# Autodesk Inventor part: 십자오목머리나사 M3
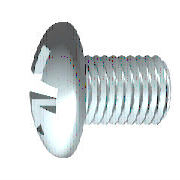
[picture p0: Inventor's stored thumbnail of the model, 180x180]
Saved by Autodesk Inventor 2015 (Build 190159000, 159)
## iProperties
Created: 2012-02
Part Number: 십자오목머리나사 M3
Material: 강철, 연강
Description: 십자 오목 머리 나사
Document SubType Name: Modeling
Standard: KS B 1023
Designer: mduedu
Standards Organization: KS
Language: ko-KR
Size Designation: A  M 3 x 6 - H
Categories: <MemberInstance><Categories><Category DisplayName="조임쇠" InternalName="e4da775c-781d-43d5-af7c-5136215cf5a6" Mnemonic="FSTN"><Category DisplayName="볼트" InternalN
Density: 7.86 g/cm^3
Appearance: 강철
Mass: 0.662353 g
Surface Area: 1.40196 cm^2
Volume: 0.0842689 cm^3
IsCustomPart: 0
Author: mduedu
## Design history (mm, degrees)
body "Solid1"
workplane "Work Plane3"
sketch "스케치2"
  geometry: L1 (-3.72, 0)-(3.72, 0) reference; L2 (0, -3.72)-(0, 3.72) reference; L3 (0, 1.5)-(0, 0); L4 (0, 0)-(1.5, 0); L5 (0, 0)-(1.879, 1.879); L6 (0.253, 1.479)-(0.261, 0.456); L7 (1.479, 0.253)-(0.456, 0.261); L8 (0.253, -1.479)-(0.261, -0.456); L9 (1.479, -0.253)-(0.456, -0.261); L10 (-0.253, 1.479)-(-0.261, 0.456); L11 (-1.479, 0.253)-(-0.456, 0.261); L12 (-1.479, -0.253)-(-0.456, -0.261); L13 (-0.253, -1.479)-(-0.261, -0.456); A1 r 0.45 centre (0, 0) between (0.45, 0) and (0, 0.45); A2 r 1.5 centre (0, 0) between (1.5, 0) and (1.479, 0.253); A3 r 1.5 centre (0, 0) between (0.253, 1.479) and (0, 1.5); A4 r 1.5 centre (0, 0) between (1.479, 0.253) and (0.253, 1.479); A5 r 1.5 centre (0, 0) between (0, -1.5) and (0.253, -1.479); A6 r 1.5 centre (0, 0) between (0.253, -1.479) and (1.479, -0.253); A7 r 1.5 centre (0, 0) between (1.479, -0.253) and (1.5, 0); A8 r 1.5 centre (0, 0) between (-1.479, 0.253) and (-1.5, 0); A9 r 1.5 centre (0, 0) between (-0.253, 1.479) and (-1.479, 0.253); A10 r 1.5 centre (0, 0) between (0, 1.5) and (-0.253, 1.479); A11 r 1.5 centre (0, 0) between (-1.5, 0) and (-1.479, -0.253); A12 r 1.5 centre (0, 0) between (-1.479, -0.253) and (-0.253, -1.479); A13 r 1.5 centre (0, 0) between (-0.253, -1.479) and (0, -1.5); A14 r 0.525 centre (0, 0) between (0.525, 0) and (0, 0.525); A15 r 0.197 centre (0.457, 0.457) between (0.261, 0.456) and (0.456, 0.261); A16 r 0.197 centre (0.457, -0.457) between (0.456, -0.261) and (0.261, -0.456); A17 r 0.197 centre (-0.457, 0.457) between (-0.456, 0.261) and (-0.261, 0.456); A18 r 0.197 centre (-0.457, -0.457) between (-0.261, -0.456) and (-0.456, -0.261); 1 further point
  constraints: 38 point on circle, 22 end point, 19 symmetric about line, 18 centre point, 4 coincident, 3 collinear, 3 point on line, 3 tangent, 1 perpendicular, 21 other
  dimensions: "d4" = 45 deg angle of L5 L4; "d5" = 0.9 diameter of A1 (= 0.3 x SDM); "d6" = 3 diameter of A4 (= SDM); "d7" = 0.2525 distance from line of L6.start L3 (= 0.5 x SBR); "d14" = 1.05 diameter of A14 (= 0.35 x SDM)
extrude "슬롯" join sketch "스케치2" taper "d15" = 5 deg; stored distance "d54" = 10
revolve "절단부" stored, may be unused: angle "d56" = 90 deg
revolve "본체" stored, may be unused: angle "d18" = 90 deg
workplane "Work Plane1"
sketch "스케치1"
  geometry: L1 (6, 0)-(6, 1.5); L2 (6, 1.5)-(1, 1.5); L3 (3.962, 5.08)-(3.962, 5.08); L4 (-2.4, 0)-(-2.4, 2.59); L5 (-2.2, 1.4)-(-1.036, 0.82); L6 (-1.036, 0.82)-(-0.6, 0); L7 (-0.6, 0)-(6, 0); L8 (-4.305, 0)-(7.717, 0) reference; L9 (0, -1.016)-(0, 6.096) reference; L10 (-2.2, 1.4)-(-2.4, 1.5); L11 (-1.636, 2.657)-(-2.4, 2.59); L12 (-1.636, 2.657)-(0, 2.8); L13 (0, 2.8)-(0, 1.347); L14 (0, 1.347)-(0.693, 1.347); L15 (0.693, 1.347)-(1, 1.5); L16 (1, 1.5)-(0, 1.5); A1 r 5 centre (2.6, 0) between (-1.636, 2.657) and (-2.4, 0)
  constraints: 28 end point, 5 point on line, 4 collinear, 4 point on circle, 3 parallel, 2 perpendicular, 1 centre point, 1 horizontal, 1 tangent
  dimensions: "d1" = 3 diameter of L2 L7 (= GD); "d2" = 1.8 distance from line of L6.end L4 (= STI); "d11" = 3 diameter of L10.end L7 (= SDM); "d12" = 62 deg angle of L6 L7; "d13" = 26.5 deg angle of L5 L7; "d17" = 5.6 diameter of L12.end L7 (= KOD); "d19" = 5 deg angle of L12 L7 (= KEWI); "d20" = 2.4 distance between parallel lines of L4 L13 (= KOH); "d21" = 5 radius of A1 (= KR); "d23" = 2.6935 diameter of L14 L7 (= BDM); "d24" = 5 distance of L1.end L2.end (= GEL); "d25" = 0.30673 horizontal distance of L14.end L2.end (= GAL); "d28" = 6 distance between parallel lines of L1 L13 (= NLG)
fillet "모깎기1" dims "d29" = 1.2 (= RR)
fillet "모깎기2" dims "d16" = 0.101 (= 0.2 x SBR)
feature "스레드" dims "d8" = 5 (= GEL), "d9" = 0
chamfer "모따기1" distance "d26" = 0.30673 (= -0.5 x SPD + 0.5 x GD); stored, may be unused: second distance "d27" = 0.30683 (computed from GUL), angle "d78" = 45 deg
other parameters: "GD" = 3 (= NND) [user parameter; used in 2 equation terms], "NLG" = 6 [user parameter; used in 1 equation term], "GEL" = 5 [user parameter; used in 2 equation terms], "KOD" = 5.6 [user parameter; used in 1 equation term], "KOH" = 2.4 [user parameter; used in 2 equation terms], "SDM" = 3 [user parameter; used in 4 equation terms], "STI" = 1.8 [user parameter; used in 1 equation term], "SBR" = 0.505 [user parameter; used in 2 equation terms], "GAL" = 0.30673 (= 0.61345 x PTC) [user parameter; used in 1 equation term], "SPD" = 2.38655 (= NND - 1.2269 x PTC) [user parameter; used in 1 equation term], "KEWI" = 5 deg [user parameter; used in 1 equation term], "d3" = -2.4 (= -KOH), "d10" = 0, "KR" = 5 [user parameter; used in 1 equation term], "BDM" = 2.6935 [user parameter; used in 1 equation term], "GUL" = 0.30673 (= 0.61345 x PTC) [user parameter; used in 1 equation term], "RR" = 1.2 [user parameter; used in 1 equation term], "d79" = 0, "d80" = 0, "PTC" = 0.5 [user parameter; used in 5 equation terms], "THREADDIA" = 3 [user parameter; used in 1 equation term], "TOA" = 30 deg [user parameter], "NND" = 3 [user parameter; used in 2 equation terms], "GD1" = 2.38655 (= THREADDIA - 1.2269 x PTC) [user parameter]
